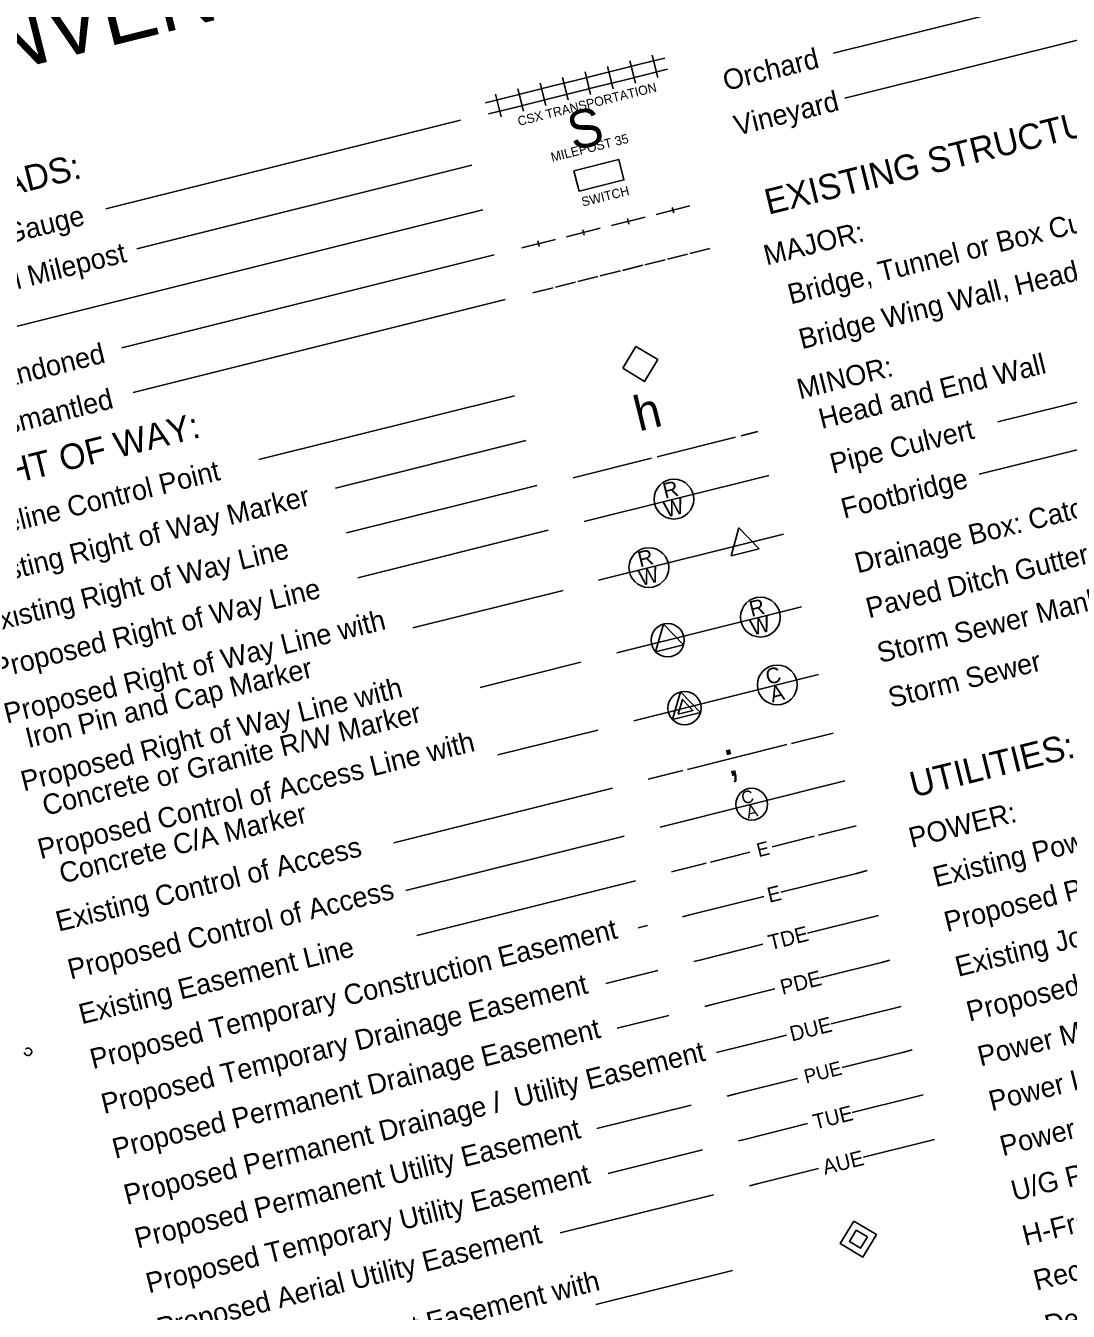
# Model space of a CAD drawing. Extents: x 1030323 to 1034123, y 654802 to 657751.
# Drawn here: x 1031236 to 1031688, y 655373 to 655929 of the extents above; entities that cross this region are included whole.
import ezdxf

# ---------------------------------------------------------------- set-up
doc = ezdxf.new("R2010")
doc.units = 0
for name, color, linetype in [('COGO Default Parcel', 7, 'Continuous'), ('Prop Easement Permanent Drainage Utility', 7, 'Continuous'), ('Prop ROW Permanent Easement CELL', 7, 'Continuous'), ('Sheet Symbology CELL', 7, 'Continuous')]:
    doc.layers.add(name, color=color, linetype=linetype)

msp = doc.modelspace()

# ---------------------------------------------------------------- linework, layer by layer
at = {"layer": 'COGO Default Parcel'}
msp.add_lwpolyline([(1031495.09, 655781.17), (1031500.79, 655790.66), (1031510.27, 655784.96), (1031504.57, 655775.48)], close=True, dxfattribs=at)
at = {"layer": 'Prop Easement Permanent Drainage Utility'}
for p, q in [((1031585.4, 655497.39), (1031615.68, 655504.94)), ((1031535.63, 655484.98), (1031566, 655492.55))]:
    msp.add_line(p, q, dxfattribs=at)
at = {"layer": 'Prop ROW Permanent Easement CELL'}
msp.add_line((1031597.14, 655404.21), (1031597.14, 655404.21), dxfattribs=at)
for points in [[(1031595.19, 655412.02), (1031604.95, 655406.16), (1031599.09, 655396.4), (1031589.32, 655402.26)], [(1031596.16, 655408.12), (1031601.04, 655405.19), (1031598.11, 655400.31), (1031593.23, 655403.24)]]:
    msp.add_lwpolyline(points, close=True, dxfattribs=at)
at = {"layer": 'Sheet Symbology CELL'}
for p, q in [((1031785.23, 655967.11), (1031586.38, 655917.54)), ((1031790.07, 655947.71), (1031591.22, 655898.13)), ((1031510.28, 655907), (1031507.86, 655916.71)), ((1031490.87, 655902.17), (1031488.45, 655911.87)), ((1031493.91, 655910.65), (1031503.61, 655913.07)), ((1031500.57, 655904.58), (1031498.15, 655914.29)), ((1031503.61, 655913.07), (1031513.31, 655915.49)), ((1031464.8, 655903.39), (1031474.5, 655905.81)), ((1031471.46, 655897.33), (1031469.05, 655907.03)), ((1031474.5, 655905.81), (1031484.2, 655908.23)), ((1031481.17, 655899.75), (1031478.75, 655909.45)), ((1031484.2, 655908.23), (1031493.91, 655910.65)), ((1031485.41, 655903.38), (1031495.12, 655905.8)), ((1031495.12, 655905.8), (1031504.82, 655908.22)), ((1031504.82, 655908.22), (1031514.52, 655910.64)), ((1031445.39, 655898.56), (1031455.1, 655900.98)), ((1031452.06, 655892.49), (1031449.64, 655902.19)), ((1031455.1, 655900.98), (1031464.8, 655903.39)), ((1031461.76, 655894.91), (1031459.34, 655904.61)), ((1031466.01, 655898.54), (1031475.71, 655900.96)), ((1031475.71, 655900.96), (1031485.41, 655903.38)), ((1031435.69, 655896.14), (1031445.39, 655898.56)), ((1031442.36, 655890.07), (1031439.94, 655899.77)), ((1031446.6, 655893.7), (1031456.31, 655896.12)), ((1031456.31, 655896.12), (1031466.01, 655898.54)), ((1031436.9, 655891.29), (1031446.6, 655893.7)), ((1031424.82, 655888.52), (1031271.11, 655850.19)), ((1031429.66, 655869.11), (1031284.55, 655832.93)), ((1031509.58, 655847.81), (1031524.13, 655851.44)), ((1031516.55, 655850.84), (1031517.15, 655848.42)), ((1031434.49, 655849.71), (1031225.97, 655797.71)), ((1031490.17, 655842.98), (1031504.72, 655846.6)), ((1031497.14, 655846), (1031497.75, 655843.58)), ((1031470.76, 655838.14), (1031485.32, 655841.77)), ((1031477.74, 655841.16), (1031478.34, 655838.74)), ((1031451.36, 655833.3), (1031465.91, 655836.93)), ((1031458.33, 655836.33), (1031458.94, 655833.9)), ((1031439.33, 655830.3), (1031278.11, 655790.1)), ((1031504.71, 655825.99), (1031513.44, 655828.17)), ((1031514.41, 655828.41), (1031523.15, 655830.59)), ((1031524.12, 655830.83), (1031532.85, 655833)), ((1031485.3, 655821.15), (1031494.04, 655823.33)), ((1031495.01, 655823.57), (1031503.74, 655825.75)), ((1031465.9, 655816.31), (1031474.63, 655818.49)), ((1031475.6, 655818.73), (1031484.33, 655820.91)), ((1031444.17, 655810.89), (1031282.94, 655770.7)), ((1031444.17, 655810.89), (1031282.94, 655770.7)), ((1031456.2, 655813.89), (1031464.93, 655816.07)), ((1031822.66, 655799.15), (1031657.53, 655757.97)), ((1031827.5, 655779.74), (1031649.48, 655735.35)), ((1031448.22, 655769.29), (1031337.4, 655741.66)), ((1031453.06, 655749.88), (1031370.64, 655729.33)), ((1031509.98, 655742.87), (1031543.94, 655751.34)), ((1031546.36, 655751.94), (1031553.64, 655753.75)), ((1031473.59, 655733.8), (1031507.55, 655742.26)), ((1031478.32, 655714.83), (1031558.37, 655734.79)), ((1031457.9, 655730.48), (1031375.48, 655709.93)), ((1031462.74, 655711.07), (1031380.32, 655690.52)), ((1031484.64, 655689.48), (1031564.69, 655709.44)), ((1031547.18, 655705.07), (1031547.18, 655705.07)), ((1031469.23, 655685.02), (1031404.11, 655668.78)), ((1031492.5, 655657.94), (1031572.55, 655677.9)), ((1031514.53, 655663.43), (1031514.53, 655663.43)), ((1031476.98, 655653.93), (1031433.33, 655643.05)), ((1031499.82, 655628.6), (1031579.87, 655648.55)), ((1031521.84, 655634.09), (1031521.84, 655634.09)), ((1031484.3, 655624.58), (1031441.01, 655613.79)), ((1031568.11, 655618.74), (1031586.18, 655623.25)), ((1031523.07, 655607.51), (1031566.17, 655618.26)), ((1031506.13, 655603.29), (1031521.13, 655607.03)), ((1031490.57, 655599.41), (1031395.92, 655575.81)), ((1031511.29, 655582.57), (1031591.34, 655602.53)), ((1031579.94, 655579.08), (1031596.18, 655583.13)), ((1031495.74, 655578.7), (1031401.09, 655555.1)), ((1031559.81, 655574.06), (1031578, 655578.59)), ((1031533.12, 655567.4), (1031550.1, 655571.64)), ((1031516.13, 655563.17), (1031531.18, 655566.92)), ((1031563.53, 655554.37), (1031596.28, 655562.54)), ((1031596.28, 655562.54), (1031601.02, 655563.72)), ((1031500.58, 655559.29), (1031405.93, 655535.69)), ((1031523.51, 655544.39), (1031556.25, 655552.56)), ((1031520.97, 655543.76), (1031523.51, 655544.39)), ((1031601.83, 655543.31), (1031605.86, 655544.31)), ((1031505.79, 655539.98), (1031501.74, 655538.97)), ((1031575.15, 655536.66), (1031601.83, 655543.31)), ((1031529.06, 655525.17), (1031555.74, 655531.82)), ((1031525.81, 655524.36), (1031529.06, 655525.17)), ((1031580.42, 655517.36), (1031607.11, 655524.01)), ((1031607.11, 655524.01), (1031610.7, 655524.91)), ((1031510.26, 655520.48), (1031487.79, 655514.88)), ((1031534.33, 655505.87), (1031561.02, 655512.52)), ((1031530.65, 655504.95), (1031534.33, 655505.87)), ((1031515.09, 655501.07), (1031492.63, 655495.47)), ((1031590.14, 655478.55), (1031616.82, 655485.2)), ((1031616.82, 655485.2), (1031620.38, 655486.09)), ((1031544.05, 655467.06), (1031570.73, 655473.71)), ((1031540.33, 655466.13), (1031544.05, 655467.06)), ((1031621.19, 655465.68), (1031625.21, 655466.68)), ((1031524.77, 655462.25), (1031483.89, 655452.06)), ((1031594.5, 655459.03), (1031621.19, 655465.68)), ((1031548.42, 655447.53), (1031575.1, 655454.19)), ((1031545.16, 655446.72), (1031548.42, 655447.53)), ((1031599.34, 655439.62), (1031626.03, 655446.27)), ((1031626.03, 655446.27), (1031630.05, 655447.28)), ((1031529.61, 655442.85), (1031488.73, 655432.65)), ((1031553.25, 655428.13), (1031579.94, 655434.78)), ((1031550, 655427.32), (1031553.25, 655428.13)), ((1031534.45, 655423.44), (1031468.03, 655406.88)), ((1031542.63, 655390.62), (1031483.43, 655375.86))]:
    msp.add_line(p, q, dxfattribs=at)
for points in [[(1031473.94, 655866.72), (1031493.35, 655871.56), (1031495.55, 655862.73), (1031476.15, 655857.89)], [(1031541.98, 655700.06), (1031545.43, 655712.06), (1031554.11, 655703.09)], [(1031509.33, 655658.43), (1031512.79, 655670.42), (1031521.46, 655661.45)], [(1031516.65, 655629.08), (1031528.78, 655632.11), (1031520.1, 655641.07)], [(1031519.13, 655631.47), (1031520.93, 655637.74), (1031525.47, 655633.05)]]:
    msp.add_lwpolyline(points, close=True, dxfattribs=at)
for centre, radius in [((1031517.25, 655724.53), 8.61), ((1031506.39, 655694.9), 8.61), ((1031554.69, 655673.45), 8.61), ((1031514.53, 655663.43), 7.2), ((1031562.01, 655644.1), 8.61), ((1031521.84, 655634.08), 7.2), ((1031550.95, 655592.46), 6.89)]:
    msp.add_circle(centre, radius, dxfattribs=at)
msp.add_arc((1031237.44, 655485.31), 1.61, 189.8976, 133.8062, dxfattribs=at)

# ---------------------------------------------------------------- texts
at = {"layer": 'Prop Easement Permanent Drainage Utility'}
msp.add_text('DUE', height=6.55, rotation=14, dxfattribs=at).set_placement((1031568.34, 655489.74))
at = {"layer": 'Sheet Symbology CELL'}
for s, height, p in [('CONVENTIONAL  PLAN SHEET SYMBOLS', 27.2003, (1031170.08, 655894.92)), ('Orchard', 8.75, (1031539.71, 655901.24)), ('CSX TRANSPORTATION', 4, (1031450.11, 655886.09)), ('Vineyard', 8.75, (1031544.55, 655881.83)), ('EXISTING STRUCTURES:', 11, (1031558.12, 655847.61)), ('S', 16.5, (1031473.62, 655875.31)), ('MILEPOST 35', 4, (1031464.49, 655870.53)), ('RAILROADS:', 11, (1031174.73, 655842.09)), ('SWITCH', 4, (1031477.77, 655851.17)), ('Standard Gauge', 8.75, (1031179.3, 655822.64)), ('Bridge, Tunnel or Box Culvert', 8.75, (1031567.8, 655808.8)), ('Bridge Wing Wall, Head Wall and End Wall', 8.75, (1031572.63, 655789.39)), ('MAJOR:', 8.75, (1031557.38, 655825.66)), ('RR Signal Milepost', 8.75, (1031184.14, 655803.23)), ('RR Abandoned', 8.75, (1031193.81, 655764.42)), ('MINOR:', 8.75, (1031571.82, 655767.74)), ('Head and End Wall', 8.75, (1031581.24, 655754.88)), ('RR Dismantled', 8.75, (1031198.65, 655745.02)), ('h', 15, (1031502.11, 655753.79)), ('RIGHT OF WAY:', 11, (1031204.09, 655724.34)), ('Pipe Culvert', 8.75, (1031586.07, 655735.48)), ('Drainage Box: Catch Basin, DI or JB', 8.75, (1031596.84, 655692.37)), ('Baseline Control Point', 8.75, (1031208.93, 655704.94)), ('Footbridge', 8.75, (1031590.93, 655716.08)), ('Existing Right of Way Marker', 8.75, (1031213.77, 655685.53)), ('R', 6.75, (1031513.41, 655724.62)), ('W', 6.75, (1031513.84, 655716.53)), ('Existing Right of Way Line', 8.75, (1031218.61, 655666.13)), ('R', 6.75, (1031502.55, 655694.99)), ('Paved Ditch Gutter', 8.75, (1031601.68, 655672.96)), ('W', 6.75, (1031502.98, 655686.9)), ('Proposed Right of Way Line', 8.75, (1031223.45, 655646.72)), ('Storm Sewer Manhole', 8.75, (1031606.52, 655653.55)), ('R', 6.75, (1031550.85, 655673.53)), ('Proposed Right of Way Line with', 8.75, (1031228.28, 655627.31)), ('W', 6.75, (1031551.28, 655665.45)), ('Storm Sewer', 8.75, (1031611.35, 655634.14)), ('  Iron Pin and Cap Marker', 8.75, (1031231.31, 655615.18)), ('C', 6.75, (1031557.92, 655644.13)), ('Proposed Right of Way Line with', 8.75, (1031235.6, 655597.99)), ('A', 6.75, (1031559.78, 655636.4)), ('  Concrete or Granite R/W Marker', 8.75, (1031238.62, 655585.86)), ('Proposed Control of Access Line with', 8.75, (1031242.91, 655568.64)), ('UTILITIES:', 11, (1031621.02, 655595.33)), (';', 15, (1031540.69, 655604.18)), ('C', 5.4, (1031547.2, 655592.36)), ('  Concrete C/A Marker', 8.75, (1031245.94, 655556.51)), ('A', 5.4, (1031549.3, 655586.2)), ('POWER:', 8.75, (1031620.25, 655573.51)), ('Existing Power Pole', 8.75, (1031630.7, 655556.53)), ('Existing Control of Access', 8.75, (1031250.73, 655537.28)), ('E', 6, (1031553.94, 655569.5)), ('Proposed Power Pole', 8.75, (1031635.54, 655537.13)), ('Proposed Control of Access', 8.75, (1031255.9, 655516.56)), ('E', 6.55, (1031558.6, 655549.74)), ('Existing Joint Use Pole', 8.75, (1031640.38, 655517.73)), ('Proposed Temporary Construction Easement', 8.75, (1031265.57, 655477.75)), ('TDE', 6.55, (1031559.06, 655529.25)), ('Existing Easement Line', 8.75, (1031260.73, 655497.16)), ('Proposed Joint Use Pole', 8.75, (1031645.23, 655498.32)), ('Proposed Temporary Drainage Easement', 8.75, (1031270.41, 655458.35)), ('PDE', 6.55, (1031564.24, 655509.93)), ('Power Manhole', 8.75, (1031650.07, 655478.91)), ('Proposed Permanent Drainage Easement', 8.75, (1031275.25, 655438.94)), ('Proposed Permanent Drainage /  Utility Easement', 8.75, (1031280.23, 655418.97)), ('Power Line Tower', 8.75, (1031654.91, 655459.52)), ('PUE', 6, (1031574.47, 655471.55)), ('Power Transformer', 8.75, (1031659.73, 655440.11)), ('TUE', 6.55, (1031578.4, 655451.61)), ('U/G Power Cable Hand Hole', 8.75, (1031664.6, 655420.7)), ('Proposed Permanent Utility Easement', 8.75, (1031284.93, 655400.12)), ('AUE', 6.55, (1031582.6, 655432.04)), ('Proposed Temporary Utility Easement', 8.75, (1031289.77, 655380.71)), ('H-Frame Pole', 8.75, (1031669.44, 655401.29)), ('Recorded U/G Power Line', 8.75, (1031674.27, 655381.89)), ('Designated U/G Power Line (S.U.E.*)', 8.75, (1031679.12, 655362.5)), ('Proposed Aerial Utility Easement', 8.75, (1031294.61, 655361.31)), ('Proposed Permanent Easement with', 8.75, (1031300.86, 655336.22))]:
    msp.add_text(s, height=height, rotation=14, dxfattribs=at).set_placement(p)

doc.saveas('drawing.dxf')
